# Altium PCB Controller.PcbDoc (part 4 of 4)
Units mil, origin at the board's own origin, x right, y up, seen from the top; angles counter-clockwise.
Board outline 5000 x 8750 mil, 6 copper layers (Top Layer, Layer 1, Layer 2, Layer 3, Layer 4, Bottom Layer), stack 92.6 mil thick; 303 components, 258 nets, 1062 pads, 274 vias.
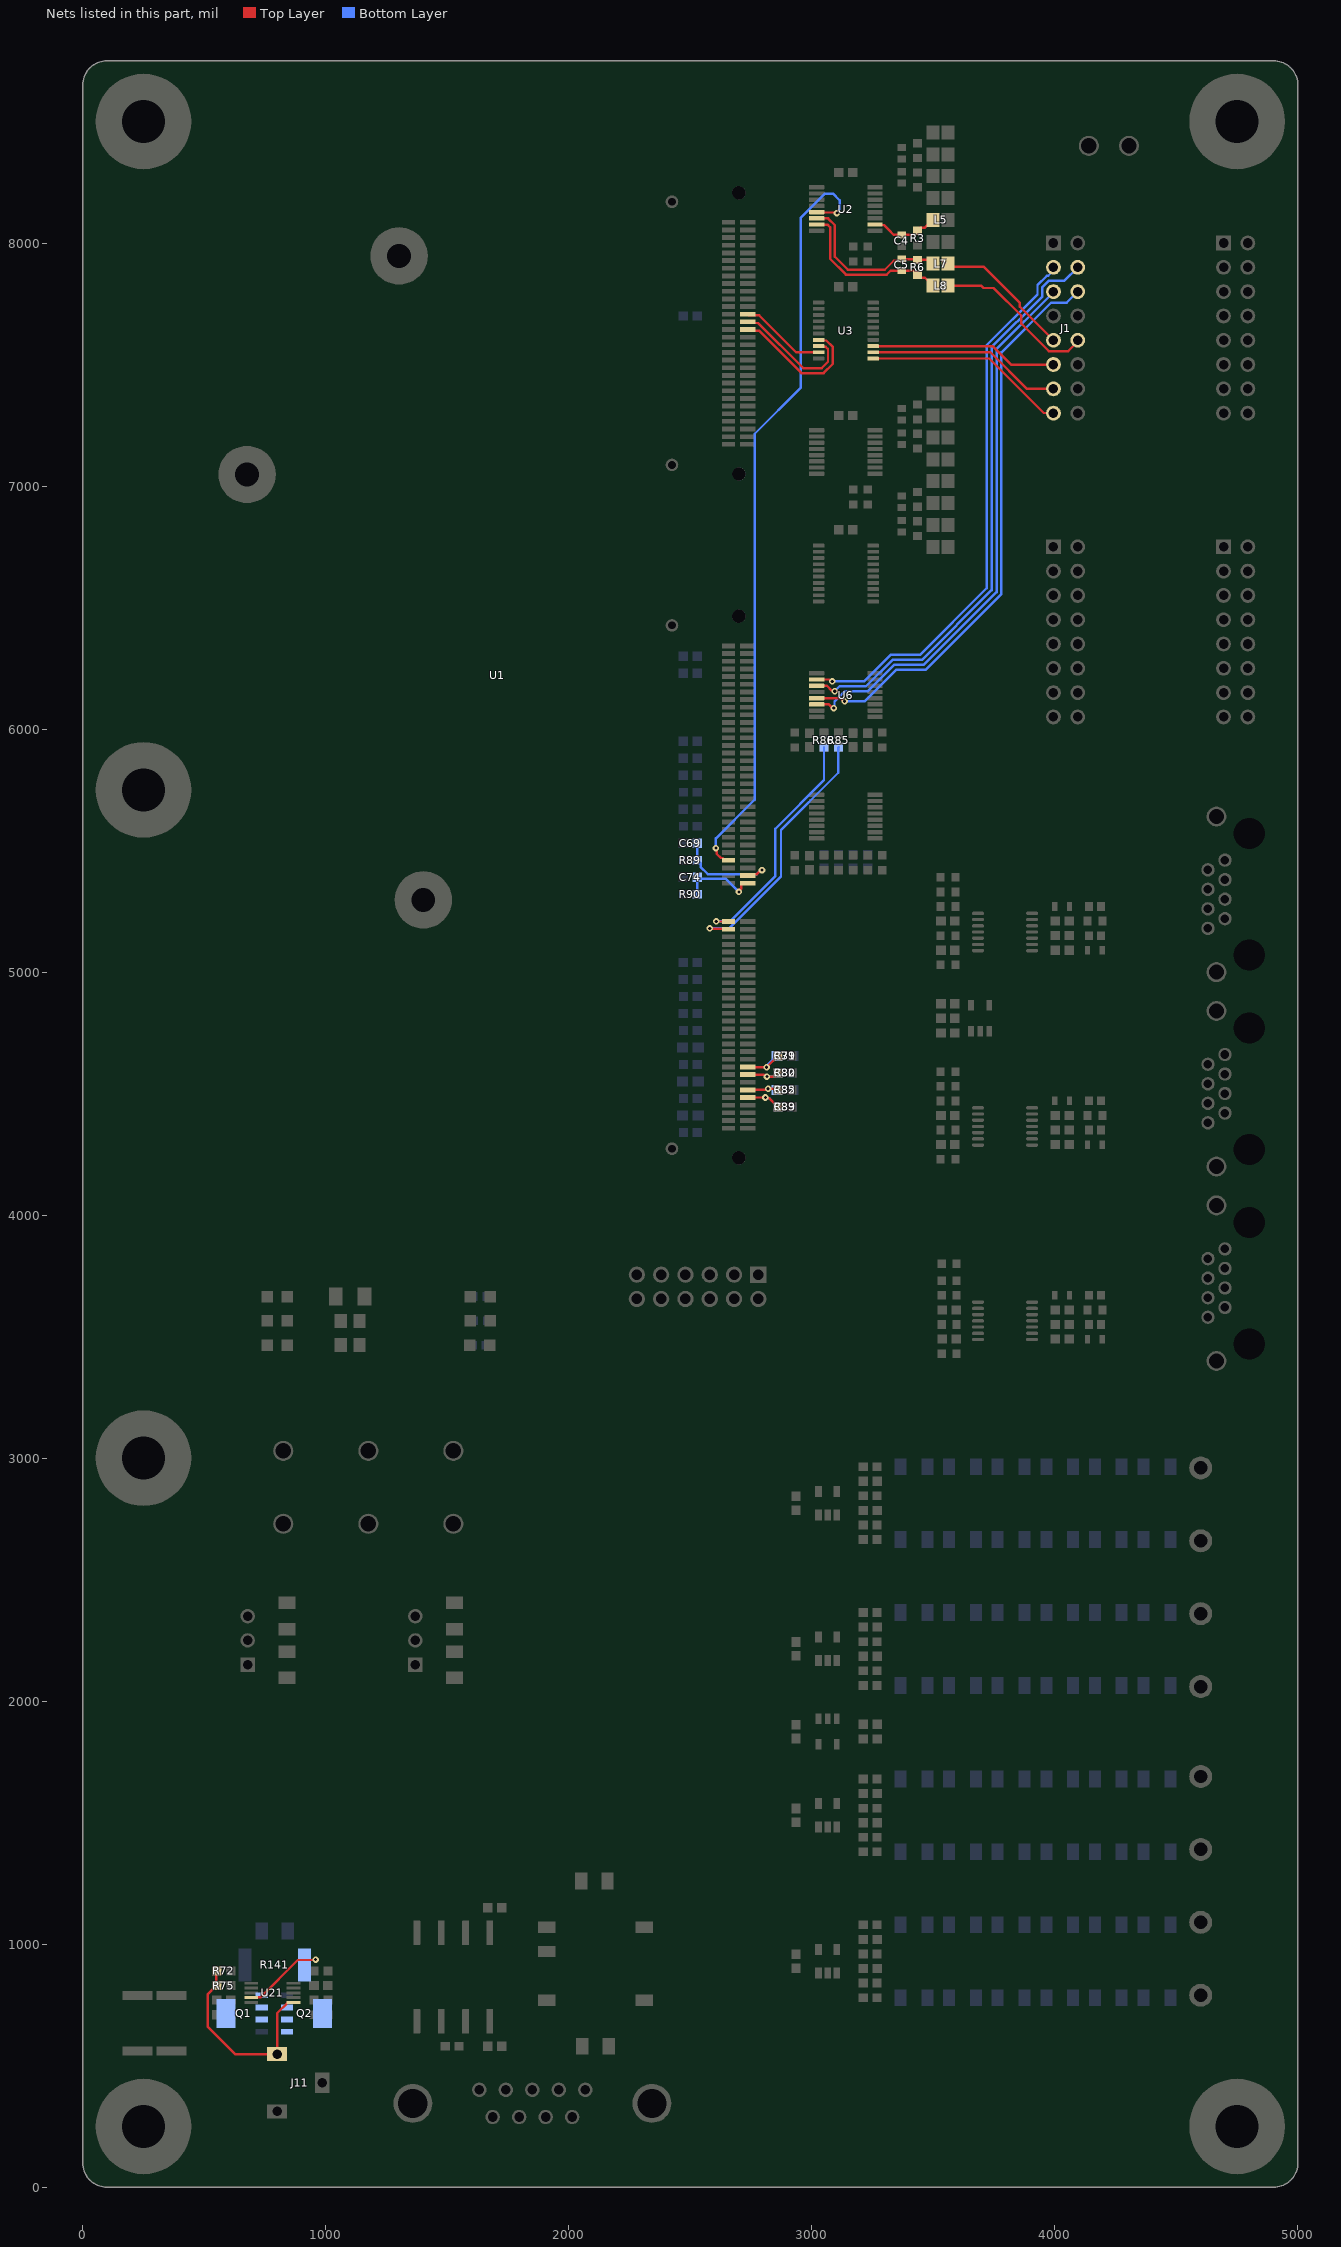
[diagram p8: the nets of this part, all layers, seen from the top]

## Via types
v1: diameter 27, hole 13, Top Layer to Bottom Layer, tented both sides, 274 vias

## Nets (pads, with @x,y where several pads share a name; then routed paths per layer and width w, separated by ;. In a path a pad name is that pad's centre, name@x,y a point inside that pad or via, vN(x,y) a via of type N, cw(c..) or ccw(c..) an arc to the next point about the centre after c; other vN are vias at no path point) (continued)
OUTB_FLT_P_FILT: C4.1 L5.2 R3.2 U2.10 | length 278
  Top Layer w10: U2.10@3260.08,8076.02 3261.81,8074.29 3296.65,8074.29 3316.96,8053.97 3337.28,8033.62 C4.1@3370,8033.62 3416.99,8033.62 3433.95,8050.58 R3.2@3435,8050.58 3446.9,8062.48 3463.39,8062.48 3493.91,8093 L5.2@3493.91,8095
OUTB_HS: R85.1 U1.54 | length 1089.7
  Top Layer w10: v1(2580,5180) 2581.61,5178.39 2656.06,5178.39 U1.54@2657.68,5176.77
  Bottom Layer w10: v1(2580,5180) 2659.75,5180 2873.12,5393.38 2873.12,5584.84 3108.5,5820.22 3108.5,5922.92 R85.1@3110,5924.42
OUTB_HS_N: J1.4 U6.11 | length 2414.4
  Top Layer w10: U6.11@3019.92,6178.39 3061.66,6178.39 3081.09,6158.96 3090.74,6158.96 v1(3093.99,6155.7)
  Bottom Layer w10: v1(3093.99,6155.7) 3114.35,6176.06 3222.93,6176.06 3331.86,6285 3453.28,6285 3740,6571.72 3740,7571.72 3948.58,7780.3 3948.58,7818.85 3975.24,7845.51 4039.61,7845.51 J1.4@4094.09,7900
OUTB_HS_P: J1.3 U6.10 | length 2299.2
  Top Layer w10: U6.10@3019.92,6203.98 3071.78,6203.98 3079.69,6196.06 v1(3084.29,6196.06)
  Bottom Layer w10: v1(3084.29,6196.06) 3214.64,6196.06 3323.58,6305 3445,6305 3720,6580 3720,7580 3928.58,7788.58 3928.58,7827.14 3966.96,7865.51 3972.5,7865.51 3994.09,7887.1 J1.3@3994.09,7900
OUTB_LEN: J1.13 U3.12 | length 804.2
  Top Layer w10: U3.12@3252.2,7550.43 3734.57,7550.43 3885,7400 J1.13@3994.09,7400
OUTB_LEN_CTRL: U1.153 U3.8 | length 515.8
  Top Layer w10: U1.153@2736.42,7675.72 2741.26,7670.87 2779.13,7670.87 2965,7485 3040,7485 3066.42,7511.42 3066.42,7534.71 3066.42,7537.5 3066.42,7563.37 3056.48,7573.31 3030.51,7573.31 U3.8@3027.8,7576.02
OUTB_LS: R86.1 U1.56 | length 983.4
  Top Layer w10: v1(2606.97,5208.5) 2607.08,5208.38 2657.56,5208.38 U1.56@2657.68,5208.27
  Bottom Layer w10: v1(2606.97,5208.5) 2663.5,5208.5 2850,5395 2850,5590 3050,5790 R86.1@3050,5924.42
OUTB_LS_N: J1.6 U6.13 | length 2360.2
  Top Layer w10: U6.13@3019.92,6127.2 3118.19,6127.2 3130.55,6114.85 v1(3134.85,6114.85)
  Bottom Layer w10: v1(3134.85,6114.85) 3218.28,6114.85 3348.43,6245 3469.85,6245 3780,6555.15 3780,6565.15 3780,7550.27 3984.22,7754.49 4048.58,7754.49 J1.6@4094.09,7800
OUTB_LS_P: J1.5 U6.14 | length 2292.8
  Top Layer w10: U6.14@3019.92,6101.61 3026.61,6101.61 3028.35,6103.35 3030,6103.35 3031.73,6101.61 3070.29,6101.61 3085.4,6086.5 v1(3090,6086.5)
  Bottom Layer w10: v1(3090,6086.5) 3093.25,6089.75 3093.25,6113.56 3135.76,6156.06 3231.21,6156.06 3340.15,6265 3461.57,6265 3760,6563.43 3760,6573.43 3760,7563.43 3994.09,7797.53 J1.5@3994.09,7800
OUTB_NTC: U1.64 U2.5 | length 3179.2
  Top Layer w10: v1(2605.08,5510.08) 2608.33,5506.82 2608.33,5486.99 2625.92,5469.39 2631.79,5469.39 2640.94,5460.24 U1.64@2657.68,5460.24 ; U2.5@3019.92,8127.2 3021.65,8125.47 3100.73,8125.47 v1(3103.09,8123.11)
  Bottom Layer w10: v1(2605.08,5510.08) 2605.15,5510.15 2605.15,5550.15 2765,5710 2765,7215.25 2955,7405.25 2955,8105 3053.5,8203.5 3086.81,8203.5 3115,8175.31 3115,8139.62 3103.09,8127.71 v1(3103.09,8123.11)
OUTB_NTC_N: J1.10 L8.1 | length 691.7
  Top Layer w10: L8.1@3556.09,7825 3696.09,7825 3706.09,7815 3747.76,7815 3861.5,7701.26 3861.5,7668.23 3975.24,7554.49 4054.49,7554.49 4094.09,7594.09 J1.10@4094.09,7600
OUTB_NTC_N_FILT: C5.2 L8.2 R6.1 U2.7 | length 669.9
  Top Layer w10: U2.7@3019.92,8076.02 3063.98,8076.02 3075,8065 3075,7935.06 3140.06,7870 3308.28,7870 3324.66,7886.38 C5.2@3370,7886.38 3416.99,7886.38 3433.95,7869.42 R6.1@3435,7869.42 3446.9,7857.52 3464.49,7857.52 3495,7827 L8.2@3495,7825
OUTB_NTC_P: J1.9 L7.1 | length 577.3
  Top Layer w10: L7.1@3556.09,7915 3568.1,7903 3706.09,7903 3856.04,7753.05 3856.04,7738.05 J1.9@3994.09,7600
OUTB_NTC_P_FILT: C5.1 L7.2 R6.2 U2.6 | length 664.6
  Top Layer w10: U2.6@3019.92,8101.61 3066.67,8101.61 3095,8073.28 3095,7943.35 3148.35,7890 3300,7890 3337.28,7927.28 3363.66,7927.28 C5.1@3370,7933.62 3431.96,7933.62 R6.2@3435,7930.58 3479.42,7930.58 L7.2@3495,7915
OUTB_OCEN: J1.15 U3.11 | length 835
  Top Layer w10: U3.11@3252.2,7524.84 3730.16,7524.84 3954.44,7300.56 3993.53,7300.56 J1.15@3994.09,7300
OUTB_OCEN_CTRL: U1.155 U3.9 | length 356.3
  Top Layer w10: U1.155@2736.42,7707.21 2741.26,7702.37 2783.5,7702.37 2935.36,7550.51 3027.72,7550.51 U3.9@3027.8,7550.43
OUTB_PSDIS: J1.11 U3.13 | length 773.4
  Top Layer w10: U3.13@3252.2,7576.02 3743.98,7576.02 3820,7500 J1.11@3994.09,7500
OUTB_PSDIS_CTRL: U1.151 U3.7 | length 579.6
  Top Layer w10: U1.151@2736.42,7644.22 2741.26,7639.38 2782.34,7639.38 2956.72,7465 3048.28,7465 3086.42,7503.13 3086.42,7571.65 3059.17,7598.9 3030.51,7598.9 U3.7@3027.8,7601.61
PWM_5A: C74.1 R90.2 U1.57 | length 331.7
  Top Layer w10: v1(2700,5330) 2700,5334.6 2708.94,5343.54 2708.94,5360.91 2713.78,5365.75 U1.57@2736.42,5365.75
  Bottom Layer w10: R90.2@2528.62,5320 R90.2@2528.62,5320 2528.58,5390.95 2534.53,5385 2645,5385 v1(2700,5330)
PWM_5B: C69.1 R89.2 U1.59 | length 424
  Top Layer w10: U1.59@2736.42,5397.24 2741.26,5402.09 2772.61,5402.09 2790.52,5420 v1(2795,5420)
  Bottom Layer w10: 2528.58,5510 R89.2@2528.62,5460 2529.53,5460 2542.48,5447.04 2542.48,5432.45 2572.43,5402.5 2772.9,5402.5 2790.4,5420 v1(2795,5420)
VAC_IN: C83.1 R39.2 U1.9 | length 194
  Top Layer w10: U1.9@2736.42,4483.86 2736.46,4483.9 v1(2808.94,4483.94) v1(2808.94,4483.94) ; 2823.73,4481.75 2860.47,4445 R39.2@2861.38,4445
  Bottom Layer w10: v1(2808.94,4483.94) 2812.19,4480.69 2824.79,4480.69 2860.47,4445 C83.1@2861.42,4445
VAC_OUT: C80.1 R32.2 U1.15 | length 187.3
  Top Layer w10: U1.15@2736.42,4578.35 2802.05,4578.35 2810.4,4570 v1(2815,4570) 2841.66,4570 2843.7,4572.04 2848.42,4572.04 R32.2@2861.38,4585
  Bottom Layer w10: v1(2815,4570) 2840.75,4570 2841.89,4571.14 2847.56,4571.14 C80.1@2861.42,4585
VDC_IN: C82.1 R35.2 U1.11 | length 168.5
  Top Layer w10: U1.11@2736.43,4515.34 2810.74,4515.34 2815.4,4520 v1(2820,4520) 2856.38,4520 R35.2@2861.38,4515
  Bottom Layer w10: v1(2820,4520) 2852.45,4520 C82.1@2857.45,4515
VDC_OUT: C79.1 R31.2 U1.17 | length 210.4
  Top Layer w10: U1.17@2736.42,4609.84 2736.92,4609.34 2813.33,4609.34 v1(2813.84,4608.84) 2814.31,4608.84 2860.47,4655 R31.2@2861.38,4655
  Bottom Layer w10: v1(2813.84,4608.84) 2817.09,4612.09 2817.09,4617.52 2854.57,4655 C79.1@2857.45,4655
VIN: J11.1 Q1.5 R72.2 R75.2 U21.1 | length 830.8
  Top Layer w10: R75.2@548.62,830 548.62,888.62 R72.2@550,890 ; R75.2@551.38,830 550.47,830 515,794.53 515,660 626.89,548.11 J11.1@800,548.11 800,715.69 844.94,760.63 U21.1@867.09,760.63
VIN_MID: Q1.1 Q1.2 Q1.3 Q2.1 Q2.2 Q2.3
VIN_PROTECT: Q2.5 R141.1 U21.9 | length 330
  Top Layer w10: U21.9@692.91,780.31 693.82,781.22 730.91,781.22 884.69,935 956.07,935 v1(958.04,936.96)
pads on no net: J5.11 J6.11 J7.11 J12.1 J12.4 J12.6 J12.8 MH1.1 MH2.1 MH3.1 MH4.1 MH6.1 U1. U1.1 U1.2 U1.3 U1.4 U1.5 U1.6 U1.8 U1.20 U1.21 U1.23 U1.25 U1.27 U1.28 U1.30 U1.31 U1.32 U1.33 U1.34 U1.36 U1.37 U1.39 U1.40 U1.41 U1.42 U1.43 U1.44 U1.45 U1.61 U1.63 U1.66 U1.67 U1.68 U1.69 U1.70 U1.71 U1.72 U1.73 U1.74 U1.75 U1.76 U1.77 U1.78 U1.79 U1.81 U1.85 U1.87 U1.89 U1.90 U1.91 U1.92 U1.93 U1.94 U1.95 U1.96 U1.99 U1.100 U1.101 U1.102 U1.103 U1.104 U1.105 U1.106 U1.107 U1.109 U1.113 U1.114 U1.115 U1.116 U1.117 U1.118 U1.119 U1.125 U1.127 U1.128 U1.129 U1.130 U1.131 U1.132 U1.133 U1.134 U1.136 U1.137 U1.138 U1.139 U1.140 U1.141 U1.148 U1.149 U1.156 U1.159 U1.160 U1.161 U1.162 U1.163 U1.164 U1.165 U1.166 U1.167 U1.168 U1.169 U1.170 U1.171 U1.172 U1.173 U1.174 U1.175 U1.176 U1.177 U1.178 U1.MH1 U1.MH2 U1.MH3 U1.MH4 U1.MH5 U1.MH6 U1.MH7 U3.17 U3.18 U5.17 U5.18 U8.1 U10.1 U11.1 U18.8
copper on no net:
  other v1: 2427.55,4510

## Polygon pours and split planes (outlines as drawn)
GND on Layer 1 "Layer 1-GND" (solid, pour order 53): 4755,3350 ccw(c4754.92,3445.08) 4850,3445.08 4850,8155 ccw(c4755.01,8155.01) 4755.03,8250 4605,8250 cw(c4605,8355) 4500,8355 4500,8505 ccw(c4405,8505) 4405.02,8600 595,8600 ccw(c594.99,8505.01) 500,8505.04 500,8355 cw(c395.01,8354.99) 395,8250 244.97,8250 ccw(c244.95,8155.05) 150,8155.08 150,6094.84 ccw(c244.85,6095) 244.85,6000.15 394.85,6000.15 cw(c394.85,5894.39) 500.61,5894.39 500.61,5605.61 cw(c395.68,5605.61) 395.68,5500.68 250,5500.68 ccw(c250,5400.68) 150,5400.68 150,3344.81 ccw(c244.85,3345) 244.85,3250.15 394.85,3250.15 cw(c394.85,3144.39) 500.61,3144.39 500.61,2855.61 cw(c395.68,2855.61) 395.68,2750.68 250,2750.68 ccw(c250,2650.68) 150,2650.68 150,1039.96 ccw(c244.96,1039.96) 244.95,945 395,945 cw(c395.01,840.03) 499.98,840.06 500,244.94 ccw(c594.95,244.95) 594.95,150 985.06,150 ccw(c985.06,244.94) 1080,244.94 1080,840 cw(c1185,840) 1185,945 2515,945 cw(c2515.01,840.01) 2620,840.03 2620,245 ccw(c2714.99,244.99) 2715,150 3295,150 ccw(c3295,245) 3390,245 3390,3245 cw(c3495,3245) 3495,3350
GND_ISO on Layer 1 "NONET_L-01_P-001" (solid, pour order 6): 1370,795 2330,795 cw(c2330.01,700.01) 2425,700 2425,245 cw(c2330.01,244.99) 2330,150 1370,150 cw(c1370,245) 1275,245 1275,700 cw(c1370,700)
+5V on Layer 3 "Layer 3-+5V" (solid, pour order 51): 151.11,2665.52 ccw(c244.94,2679.97) 244.94,2585.03 974.97,2585.03 cw(c974.96,2480) 1080,2480 1080,1965 ccw(c1176.41,1976.41) 1165,1880 2705,1880 ccw(c2696.72,1978.28) 2795,1970 2795,3255 cw(c2904.24,3240.75) 2890,3350 4755,3350 ccw(c4754.92,3445.08) 4850,3445.08 4850,8155 ccw(c4755.02,8155.02) 4755.04,8250 4605,8250 cw(c4604.99,8354.99) 4500,8355 4500,8505 ccw(c4405.01,8505.01) 4405.03,8600 595,8600 ccw(c594.98,8505.02) 500,8505.06 500,8355 cw(c395.01,8354.99) 395.02,8250 244.97,8250 ccw(c244.94,8155.06) 150,8155.07 150,6095 ccw(c241.29,6092.99) 149.98,6092.98 ccw(c242.01,6092.98) 240,6000.97 394.03,6000.97 cw(c394.04,5895.01) 500,5895 500,5605 cw(c395.03,5604.99) 395.02,5500.02 245.94,5500.94 ccw(c245.93,5405.01) 150,5405 150,3344.85 ccw(c244.84,3345) 244.85,3250.15 394.85,3250.15 cw(c394.85,3144.39) 500.61,3144.39 500.61,2855.61 cw(c395.69,2855.6) 395.68,2750.68 250,2750.68 ccw(c250,2650.68)
+3.3V on Layer 3 "NONET_L-01_P-001" (solid, pour order 29): 985,1905 ccw(c1085,1905) 1085,1805 2800,1805 ccw(c2800,1910) 2905,1910 2905,3152.95 cw(c2999.93,3155.06) 2997.83,3250 3292.82,3250 cw(c3294.86,3154.85) 3390.01,3156.87 3390.01,242.87 cw(c3294.83,245.18) 3292.5,150 2720,150 cw(c2720,250) 2620,250 2620,845 ccw(c2520,845) 2520,945 250,945 cw(c250,1045) 150,1045 150,2385 cw(c250,2385) 250,2485 885,2485 cw(c885.01,2385.01) 985,2385
+5V_ISO on Layer 3 "NONET_L-01_P-001" (solid, pour order 16): 1370,795 2330,795 cw(c2330.01,700.01) 2425,700 2425,245 cw(c2330.01,244.99) 2330,150 1370,150 cw(c1370,245) 1275,245 1275,700 cw(c1370,700)
+3.3V on Layer 2 "NONET_L-01_P-001" (solid, pour order 9): 149.99,6095.01 ccw(c245.4,6095.01) 245.41,5999.59 395.41,5999.59 cw(c395.42,5894.91) 500.1,5894.89 500.1,5605.1 cw(c395.02,5605.08) 395,5500 245,5500 ccw(c244.98,5405.03) 150.01,5405.01 150.01,3345 ccw(c244.84,3344.99) 244.84,3250.15 394.85,3250.15 cw(c394.86,3144.17) 500.84,3144.16 500.1,2855.56 cw(c395.03,2855.53) 395,2750.45 245.45,2750.45 ccw(c245.43,2655.03) 150.01,2655 150.01,2414.99 ccw(c244.99,2414.99) 245,2320 890,2320 ccw(c890,2415) 985,2415 985,5230 cw(c1088.83,5230) 1088.84,5333.84 3308.84,5333.84 ccw(c3308.84,5430) 3405,5430 3400,8505 ccw(c3305.02,8505.02) 3305,8600 605,8600 ccw(c595.01,8505.1) 500.1,8515 500.1,8354.9 cw(c395.04,8354.86) 395,8249.79 247.72,8249.79 ccw(c244.96,8154.84) 150.01,8157.51
+12V on Layer 2 "Layer 2-+12V" (solid, pour order 59): 499.98,945 1080,945 2515,945 cw(c2515.01,840.01) 2620,840.03 2620,245 ccw(c2714.99,244.99) 2715,150 3295,150 ccw(c3295,245) 3390,245 3390,3245 cw(c3495,3245) 3495,3350 4755,3350 ccw(c4754.92,3445.07) 4850,3445.07 4850,8155 ccw(c4755.01,8155.01) 4755.03,8249.99 4605,8250 cw(c4604.99,8354.99) 4500,8355 4500,8505 ccw(c4405.01,8505.01) 4405.03,8600 3595,8600 ccw(c3594.99,8505.01) 3500,8505.06 3500,5335 cw(c3395,5335) 3395.02,5230 1185,5230 ccw(c1179.97,5130.69) 1179.96,5230.13 ccw(c1179.95,5130.06) 1080,5135 1080,2325.07 cw(c974.93,2325.07) 974.93,2220 244.98,2220 ccw(c245.02,2124.98) 150,2124.97 150,2100 150,1039.94 ccw(c244.94,1039.94) 244.94,945
+5V_ISO on Layer 2 "NONET_L-01_P-001" (solid, pour order 15): 1370,795 2330,795 cw(c2330.01,700.01) 2425,700 2425,245 cw(c2330.01,244.99) 2330,150 1370,150 cw(c1370,245) 1275,245 1275,700 cw(c1370,700)
GND on Top Layer "Top Layer-GND" (solid, pour order 41): 440,1102.91 440,1130 ccw(c425,1130) 440,1130 ccw(c425,1130) 425,1145 ccw(c425,1130) 425,1145 335,1145 165,1145 ccw(c165,1130) 165,1145 ccw(c165,1130) 150,1130 ccw(c165,1130) 150,1130 150,1110 150,858.12 150,810 150,775 ccw(c165,775) 165,760 ccw(c165,775) 165,760 255,760 425,760 ccw(c425,775) 425,760 ccw(c425,775) 440,775 ccw(c425,775) 440,775 440,810
EGND on Top Layer "NONET_L-01_P-001" (solid, pour order 38): 335,590 165,590 ccw(c165,575) 150,575 150,205 440.14,205 440.14,574.86 ccw(c425,574.87) 425,590
+5V on Top Layer "NONET_L-01_P-001" (solid, pour order 36): 1349.99,2315 cw(c1349.99,2329.99) 1335,2330 1335,2430 cw(c1350,2430) 1350,2445 1560,2445 cw(c1560,2430) 1575,2430 1575,2370 cw(c1560.01,2369.99) 1560,2355 1490,2355 ccw(c1489.99,2330.01) 1465,2330 cw(c1450.01,2329.99) 1450,2315
+12V on Top Layer "NONET_L-01_P-001" (solid, pour order 35): 1349.99,2185 ccw(c1349.99,2170.01) 1335,2170 1335,2070 ccw(c1350,2070) 1350,2055 1560,2055 ccw(c1560,2070) 1575,2070 1575,2130 ccw(c1560.01,2130.01) 1560,2145 1490,2145 cw(c1489.99,2169.99) 1465,2170 ccw(c1450.01,2170.01) 1450,2185
GND on Top Layer "NONET_L-01_P-001" (solid, pour order 34): 1500,2330 ccw(c1499.99,2315.01) 1485,2315 1485,2310 cw(c1460.01,2309.99) 1460,2285 1350,2285 ccw(c1350,2270) 1335,2270 1335,2230 ccw(c1349.99,2230) 1350,2215 1460,2215 cw(c1460,2190) 1485,2190 1485,2185 ccw(c1500,2185) 1500,2170 1560,2170 ccw(c1560,2185) 1575,2185 1575,2315 ccw(c1560.01,2315.01) 1560,2330
+3.3V on Top Layer "NONET_L-01_P-001" (solid, pour order 33): 659.99,2315 cw(c659.99,2329.99) 645,2330 645,2430 cw(c660,2430) 660,2445 870,2445 cw(c870,2430) 885,2430 885,2370 cw(c870.01,2369.99) 870,2355 800,2355 ccw(c799.99,2330.01) 775,2330 cw(c760.01,2329.99) 760,2315
+12V on Top Layer "NONET_L-01_P-001" (solid, pour order 32): 659.99,2185 ccw(c659.99,2170.01) 645,2170 645,2070 ccw(c660,2070) 660,2055 870,2055 ccw(c870,2070) 885,2070 885,2130 ccw(c870.01,2130.01) 870,2145 800,2145 cw(c799.99,2169.99) 775,2170 ccw(c760.01,2170.01) 760,2185
GND on Top Layer "NONET_L-01_P-001" (solid, pour order 31): 810,2330 ccw(c809.99,2315.01) 795,2315 795,2310 cw(c770.01,2309.99) 770,2285 660,2285 ccw(c660,2270) 645,2270 645,2230 ccw(c659.99,2230) 660,2215 770,2215 cw(c770,2190) 795,2190 795,2185 ccw(c810,2185) 810,2170 870,2170 ccw(c870,2185) 885,2185 885,2315 ccw(c870.01,2315.01) 870,2330
+3.3V on Top Layer "NONET_L-01_P-001" (solid, pour order 28): 1690,1000 1690,1161.55 ccw(c1675,1161.55) 1675,1176.55 1635,1176.55 ccw(c1635,1161.55) 1620,1161.55 1620,1000 ccw(c1635,1000) 1635,985 1675,985 ccw(c1675,1000)
+5V_ISO on Top Layer "NONET_L-01_P-001" (solid, pour order 19): 2355,780 2355,555 cw(c2340,555) 2340,540 2135,540 cw(c2135,550) 2125,550 2125,780 cw(c2140,780) 2140,795 2340,795 cw(c2340,780)
+5V_ISO on Top Layer "NONET_L-01_P-001" (solid, pour order 26): 1690,730 1690,568.45 cw(c1675,568.45) 1675,553.45 1635,553.45 cw(c1635,568.45) 1620,568.45 1620,730 cw(c1635,730) 1635,745 1675,745 cw(c1675,730)
+3.3V on Top Layer "NONET_L-01_P-001" (solid, pour order 25): 1875,1020 ccw(c1875,1005) 1860,1005 1860,960 ccw(c1875,960) 1875,945 2205,945 ccw(c2205,960) 2220,960 2220,1285 ccw(c2205,1285) 2205,1300 2115,1300 ccw(c2115,1285) 2100,1285 2100,1200 cw(c2075,1200) 2075,1175 2005,1175 ccw(c2005,1160) 1990,1160 1990,1035 cw(c1975,1035) 1975,1020
GND on Top Layer "NONET_L-01_P-001" (solid, pour order 24): 2070,1300 1875,1300 ccw(c1875,1285) 1860,1285 1860,1050 ccw(c1875,1050) 1875,1035 1960,1035 ccw(c1960,1050) 1975,1050 1975,1165 cw(c2000,1165) 2000,1190 2070,1190 ccw(c2070,1205) 2085,1205 2085,1285 ccw(c2070,1285)
GND on Top Layer "NONET_L-01_P-001" (solid, pour order 22): 1360,1094.17 1360,994.17 ccw(c1375,994.17) 1375,979.17 1415,979.17 ccw(c1415,994.17) 1430,994.17 1430,1094.17 ccw(c1415,1094.17) 1415,1109.17 1375,1109.17 ccw(c1375,1094.17)
GND_ISO on Top Layer "NONET_L-01_P-001" (solid, pour order 20): 1865,780 1865,555 ccw(c1880,555) 1880,540 2085,540 ccw(c2085,550) 2095,550 2095,780 ccw(c2080,780) 2080,795 1880,795 ccw(c1880,780)
GND_ISO on Top Layer "NONET_L-01_P-001" (solid, pour order 17): 1360,730 1360,630 ccw(c1375,630) 1375,615 1415,615 ccw(c1415,630) 1430,630 1430,730 ccw(c1415,730) 1415,745 1375,745 ccw(c1375,730)
GND on Layer 4 "Layer 4-GND" (solid, pour order 55): 4755,3350 ccw(c4754.92,3445.08) 4850,3445.08 4850,8155 ccw(c4755.01,8155.01) 4755.03,8250 4605,8250 cw(c4605,8355) 4500,8355 4500,8505 ccw(c4405,8505) 4405.02,8600 595,8600 ccw(c594.99,8505.01) 500,8505.04 500,8355 cw(c395.01,8354.99) 395,8250 244.97,8250 ccw(c244.95,8155.05) 150,8155.08 150,6094.84 ccw(c244.85,6095) 244.85,6000.15 394.85,6000.15 cw(c394.85,5894.39) 500.61,5894.39 500.61,5605.61 cw(c395.68,5605.61) 395.68,5500.68 250,5500.68 ccw(c250,5400.68) 150,5400.68 150,3344.81 ccw(c244.85,3345) 244.85,3250.15 394.85,3250.15 cw(c394.85,3144.39) 500.61,3144.39 500.61,2855.61 cw(c395.68,2855.61) 395.68,2750.68 250,2750.68 ccw(c250,2650.68) 150,2650.68 150,1039.96 ccw(c244.96,1039.96) 244.95,945 395,945 cw(c395.01,840.03) 499.98,840.06 500,244.94 ccw(c594.95,244.95) 594.95,150 985.06,150 ccw(c985.06,244.94) 1080,244.94 1080,840 cw(c1185,840) 1185,945 2515,945 cw(c2515.01,840.01) 2620,840.03 2620,245 ccw(c2714.99,244.99) 2715,150 3295,150 ccw(c3295,245) 3390,245 3390,3245 cw(c3495,3245) 3495,3350
GND_ISO on Layer 4 "NONET_L-01_P-001" (solid, pour order 14): 1370,795 2330,795 cw(c2330.01,700.01) 2425,700 2425,245 cw(c2330.01,244.99) 2330,150 1370,150 cw(c1370,245) 1275,245 1275,700 cw(c1370,700)
VIN on Bottom Layer "NONET_L-01_P-001" (solid, pour order 45): 515,825 ccw(c515,810) 500,810 500,515 ccw(c515,515) 515,500 835,500 ccw(c835,515) 850,515 850,590 ccw(c835,590) 835,605 710,605 cw(c710,630) 685,630 685,810 ccw(c671.4,811.4) 670,825
VIN_PROTECT on Bottom Layer "NONET_L-01_P-001" (solid, pour order 44): 885,980 885,600 ccw(c900,600) 900,585 1065,585 ccw(c1065,600) 1080,600 1080,980 ccw(c1065,980) 1065,995 900,995 ccw(c900,980)
+12V on Bottom Layer "NONET_L-01_P-001" (solid, pour order 43): 780,1105 cw(c780,1090) 795,1090 795,855 cw(c780,855) 780,840 620,840 cw(c620,855) 605,855 605,1090 cw(c620,1090) 620,1105
VIN_MID on Bottom Layer "NONET_L-01_P-001" (solid, pour order 42): 715,805 ccw(c715,790) 700,790 700,685 ccw(c715,685) 715,670 780,670 cw(c780.01,645.01) 805,645 805,635 ccw(c820,635) 820,620 860,620 ccw(c860,635) 875,635 875,735 ccw(c860.01,735.01) 860,750 795,750 cw(c795,770) 775,770 775,790 ccw(c760,790) 760,805

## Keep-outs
Layer 1:
  lines w10: 1420,-75 ccw(c1520,-75) 1520,-175

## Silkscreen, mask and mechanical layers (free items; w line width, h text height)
Top Overlay:
  drawing of 64 lines, arcs and shapes, not listed
  text "DC" at 4360,5455.02 h60 r90
  text "OUTPUT" at 4360,4535.06 h60 r90
  text "INPUT" at 4360,3770.04 h60 r90
  text "+3.3V" at 405.09,3635 h60
  text "+5V" at 515.05,3535 h60
  text "34" at 2397.49,3445.84 h35 r90
  text "5A" at 2497.49,3445.84 h35 r90
  text "B4" at 2597.49,3445.84 h35 r90
  text "+12V" at 465.07,3435 h60
  text "3.3" at 2797.49,3431.26 h35 r90
  text "GND" at 2297.49,3428.35 h35 r90
  text "GND" at 2697.49,3428.35 h35 r90
  text "SPARE" at 1525.05,3330 h60
  text "39" at 2397.49,3295.84 h35 r90
  text "5B" at 2497.49,3295.84 h35 r90
  text "B5" at 2597.49,3295.84 h35 r90
  text "+12" at 2297.49,3281.26 h35 r90
  text "GND" at 2697.49,3278.35 h35 r90
  text "+5V" at 2797.49,3278.35 h35 r90
  text "PWR" at 2297.49,3125.7 h35 r90
  text "PWM" at 2497.49,3125.7 h35 r90
  text "ADC" at 2597.49,3125.7 h35 r90
  text "PWR" at 2747.49,3125.7 h35 r90
  text "+3.3V" at 690.04,3125 h60
  text "+5V" at 1095.03,3125 h60
  text "+12V" at 1420.03,3125 h60
  text "GPIO" at 2397.49,3096.54 h35 r90
  text "DC-" at 4484.99,2880.03 h60 r90
  text "DC+" at 4484.99,2580.03 h60 r90
  text "AC-" at 4484.99,2280.03 h60 r90
  text "OUTPUT" at 4365,2226.76 h100 r90
  text "AC+" at 4484.99,1980.03 h60 r90
  text "DC-" at 4484.99,1610.03 h60 r90
  text "DC+" at 4484.99,1310.03 h60 r90
  text "INPUT" at 4365,1015.07 h100 r90
  text "AC-" at 4484.99,1010.03 h60 r90
  text "AC+" at 4484.99,710.03 h60 r90
  text "-" at 565,374.99 h60 r180
  text "+" at 565,105 h60 r180
  text "WOLFPACK 60KW DAB / CONTROLLER STAGE / PN CRD60DD12N-GMA / V1 11/2023" at 2012.5,75 h180
  text "+12V" at 361.54,26 h35
Board Outline:
  the board outline again, w10
Drill Drawing:
  drawing of 185 lines, arcs and shapes, not listed
  text "Symbol" at 82.5,11538.94 h72
  text "Count" at 588.38,11538.94 h72
  text "Hole Size" at 1188.22,11538.94 h72
  text "Plated" at 2277.9,11538.94 h72
  text "Hole Type" at 2783.78,11538.94 h72
  text "Drill Layer Pair" at 3517.58,11538.94 h72
  text "Via/Pad" at 5017.13,11538.94 h72
  text "Pad Shape" at 5606.98,11538.94 h72
  text "Hole Tolerance (+)" at 6352.78,11538.94 h72
  text "Hole Tolerance (-)" at 7686.38,11538.94 h72
  text "Hole Length" at 9019.99,11538.94 h72
  text "Routed Path Length" at 10049.69,11538.94 h72
  text "274" at 588.38,11388.94 h60
  text "0.33mm (13.00mil)" at 1188.22,11388.94 h60
  text "PTH" at 2277.9,11388.94 h60
  text "Round" at 2783.78,11388.94 h60
  text "Top Layer - Bottom Layer" at 3517.58,11388.94 h60
  text "Via" at 5017.13,11388.94 h60
  text "Rounded" at 5606.98,11388.94 h60
  text "0.08mm (3.00mil)" at 6352.78,11388.94 h60
  text "0.08mm (3.00mil)" at 7686.38,11388.94 h60
  text "-" at 9019.99,11388.94 h60
  text "-" at 10049.69,11388.94 h60
  text "4" at 588.38,11238.94 h60
  text "0.81mm (31.89mil)" at 1188.22,11238.94 h60
  text "PTH" at 2277.9,11238.94 h60
  text "Round" at 2783.78,11238.94 h60
  text "Top Layer - Bottom Layer" at 3517.58,11238.94 h60
  text "Pad" at 5017.13,11238.94 h60
  text "Rounded" at 5606.98,11238.94 h60
  text "0.08mm (3.00mil)" at 6352.78,11238.94 h60
  text "0.08mm (3.00mil)" at 7686.38,11238.94 h60
  text "-" at 9019.99,11238.94 h60
  text "-" at 10049.69,11238.94 h60
  text "24" at 588.38,11088.94 h60
  text "0.89mm (35.04mil)" at 1188.22,11088.94 h60
  text "PTH" at 2277.9,11088.94 h60
  text "Round" at 2783.78,11088.94 h60
  text "Top Layer - Bottom Layer" at 3517.58,11088.94 h60
  text "Pad" at 5017.13,11088.94 h60
  text "Rounded" at 5606.98,11088.94 h60
  text "0.08mm (3.00mil)" at 6352.78,11088.94 h60
  text "0.08mm (3.00mil)" at 7686.38,11088.94 h60
  text "-" at 9019.99,11088.94 h60
  text "-" at 10049.69,11088.94 h60
  text "79" at 588.38,10938.94 h60
  text "1.00mm (39.37mil)" at 1188.22,10938.94 h60
  text "PTH" at 2277.9,10938.94 h60
  text "Round" at 2783.78,10938.94 h60
  text "Top Layer - Bottom Layer" at 3517.58,10938.94 h60
  text "Pad" at 5017.13,10938.94 h60
  text "(Mixed)" at 5606.98,10938.94 h60
  text "0.08mm (3.00mil)" at 6352.78,10938.94 h60
  text "0.08mm (3.00mil)" at 7686.38,10938.94 h60
  text "-" at 9019.99,10938.94 h60
  text "-" at 10049.69,10938.94 h60
  text "3" at 588.38,10788.94 h60
  text "1.00mm (39.37mil)" at 1188.22,10788.94 h60
  text "PTH" at 2277.9,10788.94 h60
  text "Slot" at 2783.78,10788.94 h60
  text "Top Layer - Bottom Layer" at 3517.58,10788.94 h60
  text "Pad" at 5017.13,10788.94 h60
  text "Rectangle" at 5606.98,10788.94 h60
  text "0.08mm (3.00mil)" at 6352.78,10788.94 h60
  text "0.08mm (3.00mil)" at 7686.38,10788.94 h60
  text "1.60mm (62.99mil)" at 9019.99,10788.94 h60
  text "0.60mm (23.62mil)" at 10049.69,10788.94 h60
  text "12" at 588.38,10638.94 h60
  text "1.10mm (43.31mil)" at 1188.22,10638.94 h60
  text "PTH" at 2277.9,10638.94 h60
  text "Round" at 2783.78,10638.94 h60
  text "Top Layer - Bottom Layer" at 3517.58,10638.94 h60
  text "Pad" at 5017.13,10638.94 h60
  text "(Mixed)" at 5606.98,10638.94 h60
  text "0.08mm (3.00mil)" at 6352.78,10638.94 h60
  text "0.08mm (3.00mil)" at 7686.38,10638.94 h60
  text "-" at 9019.99,10638.94 h60
  text "-" at 10049.69,10638.94 h60
  text "4" at 588.38,10488.94 h60
  text "1.40mm (55.12mil)" at 1188.22,10488.94 h60
  text "NPTH" at 2277.9,10488.94 h60
  text "Round" at 2783.78,10488.94 h60
  text "Top Layer - Bottom Layer" at 3517.58,10488.94 h60
  text "Pad" at 5017.13,10488.94 h60
  text "Rounded" at 5606.98,10488.94 h60
  text "0.08mm (3.00mil)" at 6352.78,10488.94 h60
  text "0.08mm (3.00mil)" at 7686.38,10488.94 h60
  text "-" at 9019.99,10488.94 h60
  text "-" at 10049.69,10488.94 h60
  text "8" at 588.38,10338.94 h60
  text "1.40mm (55.12mil)" at 1188.22,10338.94 h60
  text "PTH" at 2277.9,10338.94 h60
  text "Round" at 2783.78,10338.94 h60
  text "Top Layer - Bottom Layer" at 3517.58,10338.94 h60
  text "Pad" at 5017.13,10338.94 h60
  text "Rounded" at 5606.98,10338.94 h60
  text "0.08mm (3.00mil)" at 6352.78,10338.94 h60
  text "0.08mm (3.00mil)" at 7686.38,10338.94 h60
  text "-" at 9019.99,10338.94 h60
  text "-" at 10049.69,10338.94 h60
  text "6" at 588.38,10188.94 h60
  text "1.57mm (61.81mil)" at 1188.22,10188.94 h60
  text "PTH" at 2277.9,10188.94 h60
  text "Round" at 2783.78,10188.94 h60
  text "Top Layer - Bottom Layer" at 3517.58,10188.94 h60
  text "Pad" at 5017.13,10188.94 h60
  text "Rounded" at 5606.98,10188.94 h60
  text "0.08mm (3.00mil)" at 6352.78,10188.94 h60
  text "0.08mm (3.00mil)" at 7686.38,10188.94 h60
  text "-" at 9019.99,10188.94 h60
  text "-" at 10049.69,10188.94 h60
  text "8" at 588.38,10038.94 h60
  text "1.60mm (62.99mil)" at 1188.22,10038.94 h60
  text "PTH" at 2277.9,10038.94 h60
  text "Round" at 2783.78,10038.94 h60
  text "Top Layer - Bottom Layer" at 3517.58,10038.94 h60
  text "Pad" at 5017.13,10038.94 h60
  text "Rounded" at 5606.98,10038.94 h60
  text "0.08mm (3.00mil)" at 6352.78,10038.94 h60
  text "0.08mm (3.00mil)" at 7686.38,10038.94 h60
  text "-" at 9019.99,10038.94 h60
  text "-" at 10049.69,10038.94 h60
  text "3" at 588.38,9888.94 h60
  text "2.49mm (98.00mil)" at 1188.22,9888.94 h60
  text "PTH" at 2277.9,9888.94 h60
  text "Round" at 2783.78,9888.94 h60
  text "Top Layer - Bottom Layer" at 3517.58,9888.94 h60
  text "Pad" at 5017.13,9888.94 h60
  text "Rounded" at 5606.98,9888.94 h60
  text "0.13mm (5.00mil)" at 6352.78,9888.94 h60
  text "0.13mm (5.00mil)" at 7686.38,9888.94 h60
  text "-" at 9019.99,9888.94 h60
  text "-" at 10049.69,9888.94 h60
  text "2" at 588.38,9738.94 h60
  text "3.05mm (120.08mil)" at 1188.22,9738.94 h60
  text "PTH" at 2277.9,9738.94 h60
  text "Round" at 2783.78,9738.94 h60
  text "Top Layer - Bottom Layer" at 3517.58,9738.94 h60
  text "Pad" at 5017.13,9738.94 h60
  text "Rounded" at 5606.98,9738.94 h60
  text "0.13mm (5.00mil)" at 6352.78,9738.94 h60
  text "0.13mm (5.00mil)" at 7686.38,9738.94 h60
  text "-" at 9019.99,9738.94 h60
  text "-" at 10049.69,9738.94 h60
  text "6" at 588.38,9588.94 h60
  text "3.25mm (127.95mil)" at 1188.22,9588.94 h60
  text "NPTH" at 2277.9,9588.94 h60
  text "Round" at 2783.78,9588.94 h60
  text "Top Layer - Bottom Layer" at 3517.58,9588.94 h60
  text "Pad" at 5017.13,9588.94 h60
  text "Rounded" at 5606.98,9588.94 h60
  text "0.13mm (5.00mil)" at 6352.78,9588.94 h60
  text "0.13mm (5.00mil)" at 7686.38,9588.94 h60
  text "-" at 9019.99,9588.94 h60
  text "-" at 10049.69,9588.94 h60
  text "6" at 588.38,9438.94 h60
  text "4.50mm (177.17mil)" at 1188.22,9438.94 h60
  text "PTH" at 2277.9,9438.94 h60
  text "Round" at 2783.78,9438.94 h60
  text "Top Layer - Bottom Layer" at 3517.58,9438.94 h60
  text "Pad" at 5017.13,9438.94 h60
  text "Rounded" at 5606.98,9438.94 h60
  text "0.13mm (5.00mil)" at 6352.78,9438.94 h60
  text "0.13mm (5.00mil)" at 7686.38,9438.94 h60
  text "-" at 9019.99,9438.94 h60
  text "-" at 10049.69,9438.94 h60
  text "439 Total" at 588.38,9288.94 h60
  text "Slot definitions :" at 82.5,9143.97 h60
  text "Routed Path Length" at 1115.19,9143.97 h60
  text "= Calculated from tool start centre position to tool end centre position." at 2217.86,9143.97 h60
  text "Hole Length" at 1115.19,9043.99 h60
  text "= Routed Path Length + Tool Size = Slot length as defined in the PCB layout" at 1807.99,9043.99 h60

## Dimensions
100,0 to 100,8750 on Drill Drawing
0,100 to 5000,100 on Drill Drawing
